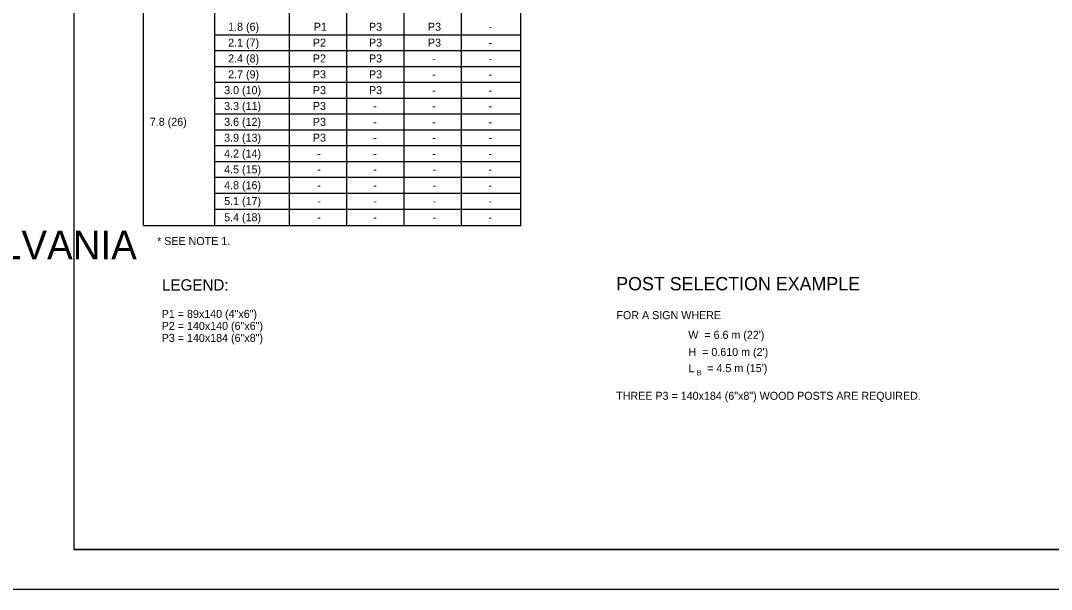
# Model space of a CAD drawing. Extents: x -1958 to 628, y -879 to 309.
# Drawn here: x -256.4 to 130.1, y -284.6 to -71.3 of the extents above; entities that cross this region are included whole.
import ezdxf

# ---------------------------------------------------------------- set-up
doc = ezdxf.new("R2010")
doc.units = 0
for name, color, linetype in [('1', 7, 'Continuous'), ('2', 7, 'Continuous'), ('3', 7, 'Continuous'), ('4', 7, 'Continuous'), ('PLT-BNDY', 7, 'Continuous')]:
    doc.layers.add(name, color=color, linetype=linetype)

msp = doc.modelspace()

# ---------------------------------------------------------------- linework, layer by layer
at = {"layer": '1'}
for p, q in [((-236.39, 294.44), (-236.39, -269.56)), ((-210.36, -148.17), (-210.36, 265.3)), ((-68.88, -148.17), (-68.88, 265.3)), ((-183.56, -148.17), (-183.56, 257.63)), ((-155.55, -148.17), (-155.55, 257.63)), ((-134.05, -148.17), (-134.05, 250.28)), ((-112.55, -148.17), (-112.55, 250.28)), ((-91.05, -148.17), (-91.05, 250.28)), ((549.61, -269.56), (-236.39, -269.56)), ((-236.39, -269.56), (349.61, -269.56))]:
    msp.add_line(p, q, dxfattribs=at)
at = {"layer": '2'}
for p, q in [((-183.56, -76.62), (-68.88, -76.62)), ((-183.56, -82.56), (-68.88, -82.56)), ((-108.57, -82.56), (-72.93, -82.56)), ((-183.56, -88.5), (-68.88, -88.5)), ((-183.56, -94.44), (-68.88, -94.44)), ((-108.57, -94.44), (-72.93, -94.44)), ((-183.56, -100.38), (-68.88, -100.38)), ((-183.56, -106.32), (-68.88, -106.32)), ((-108.57, -106.32), (-72.93, -106.32)), ((-183.56, -112.26), (-68.88, -112.26)), ((-183.56, -118.2), (-68.88, -118.2)), ((-183.56, -124.14), (-68.88, -124.14)), ((-183.56, -130.08), (-68.88, -130.08)), ((-183.56, -136.02), (-68.88, -136.02)), ((-183.56, -141.96), (-68.88, -141.96)), ((-210.36, -148.17), (-68.88, -148.17))]:
    msp.add_line(p, q, dxfattribs=at)
at = {"layer": 'PLT-BNDY'}
msp.add_lwpolyline([(-276.39, 309.44), (564.61, 309.44), (564.61, -284.56), (-276.39, -284.56)], close=True, dxfattribs=at)

# ---------------------------------------------------------------- texts
at = {"layer": '1'}
for s, height, p in [('COMMONWEALTH OF PENNSYLVANIA', 10.7827, (-478.79, -160.83)), ('FOR A SIGN WHERE ', 3, (-33, -183.25)), ("W  = 6.6 m (22')", 3, (-6.05, -190.63)), ("H  = 0.610 m (2')", 3, (-5.99, -197.05)), ('L', 3, (-6.04, -203.2)), (" = 4.5 m (15')", 3, (-0.06, -203.12)), ('B', 2, (-2.9, -204.26)), ('THREE P3 = 140x184 (6"x8") WOOD POSTS ARE REQUIRED.', 3, (-33.1, -213.49))]:
    msp.add_text(s, height=height, dxfattribs=at).set_placement(p)
at = {"layer": '2'}
for s, height, p in [('1.8 (6)', 3, (-178.57, -75.14)), ('P1', 3, (-146.47, -75.14)), ('P3', 3, (-125.78, -75.14)), ('P3', 3, (-103.67, -75.14)), ('-', 3, (-80.97, -75.14)), ('2.1 (7)', 3, (-178.57, -81.08)), ('P2', 3, (-146.81, -81.08)), ('P3', 3, (-125.78, -81.08)), ('P3', 3, (-103.67, -81.08)), ('-', 3, (-80.97, -81.08)), ('2.4 (8)', 3, (-178.57, -87.02)), ('P2', 3, (-146.81, -87.02)), ('P3', 3, (-125.78, -87.02)), ('-', 3, (-102.05, -87.02)), ('-', 3, (-80.97, -87.02)), ('2.7 (9)', 3, (-178.57, -92.96)), ('P3', 3, (-146.81, -92.96)), ('P3', 3, (-125.78, -92.96)), ('-', 3, (-102.05, -92.96)), ('-', 3, (-80.97, -92.96)), ('3.0 (10)', 3, (-180.07, -98.9)), ('P3', 3, (-146.81, -98.9)), ('P3', 3, (-125.78, -98.9)), ('-', 3, (-102.05, -98.9)), ('-', 3, (-80.97, -98.9)), ('3.3 (11)', 3, (-180.07, -104.84)), ('P3', 3, (-146.81, -104.84)), ('-', 3, (-124.16, -104.84)), ('-', 3, (-102.05, -104.84)), ('-', 3, (-80.97, -104.84)), ('7.8 (26)', 3, (-207.93, -110.75)), ('3.6 (12)', 3, (-180.07, -110.78)), ('P3', 3, (-146.81, -110.78)), ('-', 3, (-124.16, -110.78)), ('-', 3, (-102.05, -110.78)), ('-', 3, (-80.97, -110.78)), ('3.9 (13)', 3, (-180.07, -116.72)), ('P3', 3, (-146.81, -116.72)), ('-', 3, (-124.16, -116.72)), ('-', 3, (-102.05, -116.72)), ('-', 3, (-80.97, -116.72)), ('4.2 (14)', 3, (-180.07, -122.66)), ('-', 3, (-145.19, -122.66)), ('-', 3, (-124.16, -122.66)), ('-', 3, (-102.05, -122.66)), ('-', 3, (-81.01, -122.66)), ('4.5 (15)', 3, (-180.07, -128.6)), ('-', 3, (-145.15, -128.6)), ('-', 3, (-124.16, -128.6)), ('-', 3, (-101.88, -128.6)), ('-', 3, (-81.01, -128.6)), ('4.8 (16)', 3, (-180.07, -134.54)), ('-', 3, (-145.15, -134.54)), ('-', 3, (-124.16, -134.54)), ('-', 3, (-101.88, -134.54)), ('-', 3, (-81.01, -134.54)), ('5.1 (17)', 3, (-180.07, -140.48)), ('-', 3, (-145.15, -140.48)), ('-', 3, (-124.16, -140.48)), ('-', 3, (-101.88, -140.48)), ('-', 3, (-81.01, -140.48)), ('5.4 (18)', 3, (-180.07, -146.56)), ('-', 3, (-145.15, -146.56)), ('-', 3, (-124.16, -146.56)), ('-', 3, (-101.88, -146.56)), ('-', 3, (-81.01, -146.56)), ('POST SELECTION EXAMPLE', 5, (-33.08, -172.45))]:
    msp.add_text(s, height=height, dxfattribs=at).set_placement(p)
at = {"layer": '3'}
for s, height, p in [('* SEE NOTE 1.', 3, (-205.22, -155.47)), ('LEGEND:', 4.25, (-203.37, -172.55))]:
    msp.add_text(s, height=height, dxfattribs=at).set_placement(p)
at = {"layer": '4'}
for s, p in [('P1 = 89x140 (4"x6")', (-203.49, -182.78)), ('P2 = 140x140 (6"x6")', (-203.49, -187.28)), ('P3 = 140x184 (6"x8")', (-203.49, -191.78))]:
    msp.add_text(s, height=3, dxfattribs=at).set_placement(p)

doc.saveas('drawing.dxf')
